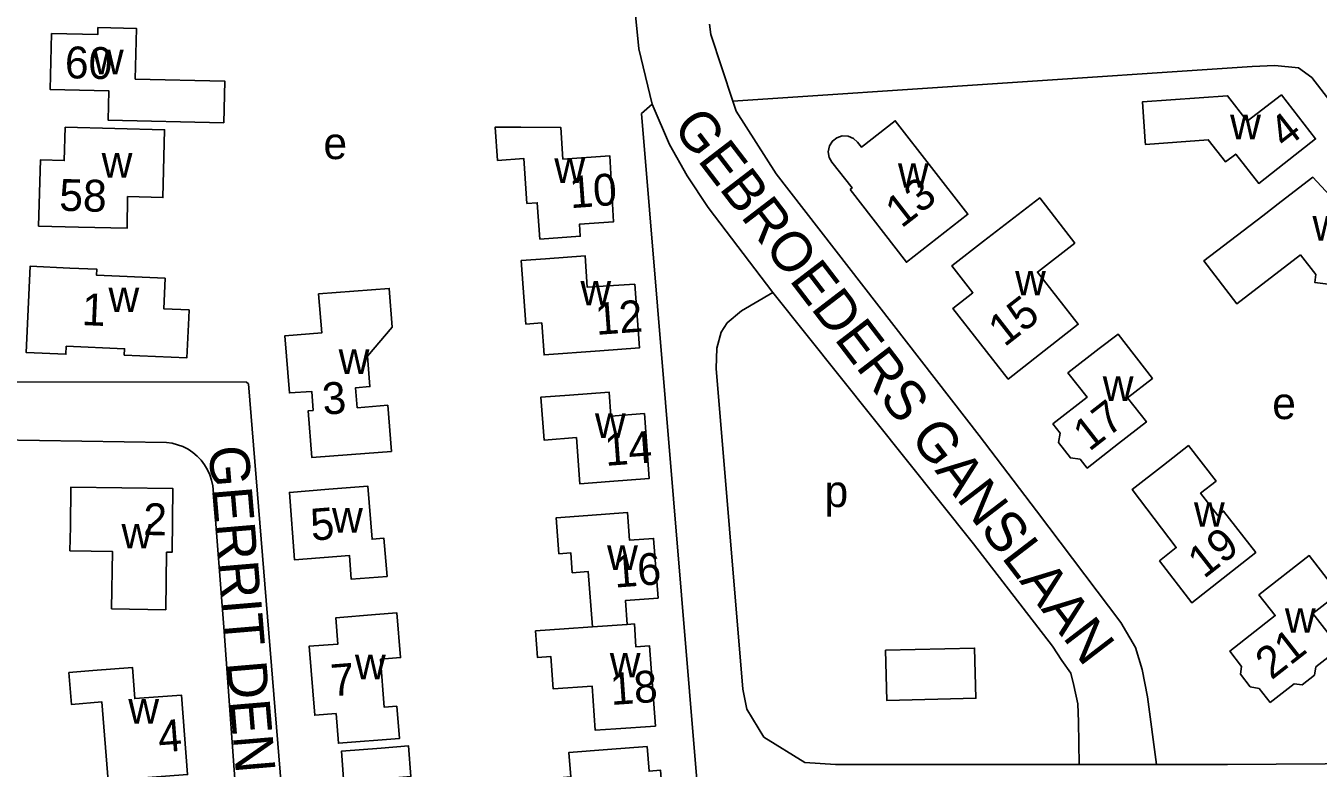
# Model space of a CAD drawing. Extents: x 156721 to 158827, y 386657 to 388950.
# Drawn here: x 158252.9 to 158415.3, y 387600.8 to 387694 of the extents above; entities that cross this region are included whole.
import ezdxf

# ---------------------------------------------------------------- set-up
doc = ezdxf.new("R2010")
doc.units = 0
for name, color, linetype in [('BLT_Basislijn', 7, 'Continuous'), ('BLT_Bebouwing', 7, 'Continuous'), ('BLT_Centroide', 7, 'Continuous'), ('BLT_Huisnummer', 7, 'Continuous'), ('BLT_Onderverdeling_panden', 7, 'Continuous'), ('BLT_Straatnaam', 7, 'Continuous')]:
    doc.layers.add(name, color=color, linetype=linetype)

msp = doc.modelspace()

# ---------------------------------------------------------------- linework, layer by layer
at = {"layer": 'BLT_Basislijn'}
for p, q in [((158270.59, 387641.69), (158233.87, 387642.27)), ((158276.47, 387635.81), (158277.84, 387617.97)), ((158283.92, 387534.66), (158277.84, 387617.97)), ((158385.24, 387601.28), (158394.96, 387601.28))]:
    msp.add_line(p, q, dxfattribs=at)
for points in [[(158331.61, 387684.16), (158329.92, 387691.11), (158327.69, 387713.57), (158325.62, 387716.63), (158322.75, 387717.43), (158319.65, 387717.59), (158249.95, 387717.76)], [(158341.75, 387684.53), (158338.99, 387692.89), (158338.81, 387694.19)], [(158341.75, 387684.53), (158406.99, 387688.87), (158409.83, 387689.02), (158412.81, 387688.72), (158414.45, 387687.52), (158443.84, 387649.45), (158458.24, 387631.46), (158460.33, 387628.78), (158461.37, 387623.55), (158461.08, 387617.73), (158461.22, 387601.86)], [(158394.96, 387601.28), (158393.82, 387609.78), (158393.15, 387613.21), (158392.33, 387615.97), (158390.46, 387619.11), (158379.89, 387633.11), (158372.66, 387642.56), (158347.18, 387675.42), (158342.17, 387683.26), (158341.75, 387684.53)], [(158331.61, 387684.16), (158330.27, 387682.97), (158337.29, 387598.34), (158342.49, 387594.21), (158431.88, 387594.8), (158432.5, 387594.66), (158434.94, 387592.24), (158434.85, 387566.34), (158432.92, 387555.36), (158430.15, 387548.17), (158421.36, 387530.67), (158420.31, 387528.76), (158417.02, 387526.27), (158293.15, 387534.97), (158290, 387537.72), (158280.9, 387649.05), (158280.63, 387649.25), (158242.83, 387649.3)], [(158331.61, 387684.16), (158333.76, 387679.1), (158336, 387675.16), (158338.65, 387671.18), (158346.78, 387660.53)], [(158346.78, 387660.53), (158342.83, 387658.21), (158341.02, 387656.7), (158340.29, 387655.56), (158339.73, 387653.53), (158339.66, 387650.98), (158343.01, 387610.73), (158343.48, 387608.22), (158345.62, 387604.72), (158350.79, 387601.54), (158354.62, 387601.3), (158385.24, 387601.28)], [(158385.24, 387601.28), (158385.17, 387606.64), (158385.09, 387608.88), (158384.57, 387611.2), (158384.2, 387612.76), (158383.08, 387614.33), (158381.89, 387616.12), (158371.96, 387628.96), (158346.78, 387660.53)], [(158270.59, 387641.69), (158271.3, 387641.6), (158272, 387641.42), (158272.67, 387641.17), (158273.31, 387640.84), (158273.9, 387640.44), (158274.46, 387639.98), (158274.95, 387639.47), (158275.39, 387638.9), (158275.75, 387638.28), (158276.05, 387637.63), (158276.27, 387636.95), (158276.42, 387636.25), (158276.47, 387635.81)], [(158394.96, 387601.28), (158396.6, 387601.27), (158403.89, 387601.3), (158452.92, 387601.61), (158461.22, 387601.86)]]:
    msp.add_lwpolyline(points, dxfattribs=at)
msp.add_lwpolyline([(158360.91, 387615.62), (158372.11, 387615.89), (158372.26, 387609.6), (158361.06, 387609.33)], close=True, dxfattribs=at)
at = {"layer": 'BLT_Bebouwing'}
for points in [[(158266.67, 387687.29), (158266.82, 387693.65), (158261.98, 387693.77), (158261.96, 387692.88), (158256.16, 387693.02), (158255.97, 387686), (158263.35, 387685.83), (158263.27, 387682.16), (158277.8, 387681.82), (158277.93, 387687.02), (158266.67, 387687.29)], [(158411, 387676.71), (158407.79, 387674.2), (158404.91, 387677.89), (158403.63, 387676.9), (158401.46, 387679.69), (158393.56, 387679.1), (158393.54, 387679.47), (158393.21, 387684.46), (158403.89, 387685.21), (158406.36, 387682.02), (158410.64, 387685.31), (158414.93, 387679.8), (158411, 387676.71)], [(158257.86, 387681.27), (158270.36, 387680.95), (158270.14, 387672.43), (158265.72, 387672.55), (158265.64, 387668.58), (158259.53, 387668.73), (158254.53, 387668.86), (158254.77, 387677.15), (158257.76, 387677.08), (158257.86, 387681.27)], [(158317.5, 387667.22), (158317.17, 387671.78), (158315.88, 387671.69), (158315.48, 387677.34), (158312.18, 387677.1), (158311.89, 387681.27), (158315.11, 387681.25), (158320.11, 387681.23), (158320.39, 387677.26), (158326.27, 387677.68), (158326.75, 387669.39), (158322.47, 387669.08), (158322.56, 387667.58), (158317.5, 387667.22)], [(158357.39, 387679.39), (158357.88, 387678.77), (158362.14, 387682.08), (158371.26, 387670.33), (158363.55, 387664.32), (158356.47, 387673.46)], [(158357.39, 387679.39), (158356.89, 387679.85), (158356.21, 387680.14), (158355.46, 387680.16), (158354.78, 387679.94), (158354.26, 387679.53), (158353.87, 387678.93), (158353.72, 387678.19), (158353.83, 387677.46), (158354.16, 387676.87)], [(158356.47, 387673.46), (158356.71, 387673.65), (158354.16, 387676.87)], [(158421.52, 387663.23), (158425.44, 387666.33), (158419.04, 387674.51), (158416.71, 387672.71), (158414.59, 387674.98), (158410.62, 387671.94), (158408.29, 387670.16)], [(158380.27, 387652.73), (158385.13, 387656.53), (158379.99, 387663.07), (158384.69, 387666.71), (158380.29, 387672.39), (158373.21, 387666.94), (158369.25, 387663.88), (158371.9, 387660.49), (158369.39, 387658.51), (158376.33, 387649.65), (158380.27, 387652.73)], [(158408.29, 387670.16), (158400.9, 387664.51), (158405.04, 387659.11), (158413.03, 387665.23)], [(158325.02, 387653.21), (158318.03, 387652.69), (158317.74, 387656.7), (158315.74, 387656.55), (158315.16, 387664.52), (158318.2, 387664.75), (158323.18, 387665.13), (158323.44, 387661.17), (158329.42, 387661.56), (158330.01, 387653.57), (158325.02, 387653.21)], [(158413.03, 387665.23), (158414.95, 387662.77), (158414.83, 387661.78), (158419.9, 387661.15), (158420.01, 387662.04), (158421.52, 387663.23)], [(158273.39, 387657.33), (158273.44, 387658.33), (158270.25, 387658.47), (158270.42, 387662.3), (158261.82, 387662.68), (158261.85, 387663.44), (158258.46, 387663.59), (158253.46, 387663.81), (158252.97, 387652.99), (158257.97, 387652.77), (158258.01, 387653.78), (158265.33, 387653.46), (158265.29, 387652.67), (158273.16, 387652.33), (158273.39, 387657.33)], [(158293.85, 387640.18), (158298.84, 387640.58), (158298.38, 387646.36), (158294.55, 387646.05), (158294.35, 387648.57), (158296.16, 387648.71), (158295.86, 387652.53), (158298.96, 387656.15), (158298.57, 387661.04), (158289.71, 387660.35), (158290.1, 387655.45), (158285.48, 387655.09), (158286.04, 387647.92), (158288.84, 387648.11), (158289.01, 387645.72), (158288.4, 387645.68), (158288.86, 387639.79), (158293.85, 387640.18)], [(158390.2, 387641.56), (158393.69, 387644.27), (158391.33, 387647.3), (158394.44, 387649.73), (158390.12, 387655.3), (158387.77, 387653.49), (158383.82, 387650.43), (158386.24, 387647.37), (158381.95, 387644.03), (158382.84, 387642.87), (158382.66, 387641.68), (158384.13, 387639.76), (158385.36, 387639.61), (158386.26, 387638.48), (158390.2, 387641.56)], [(158326.23, 387636.79), (158331.22, 387637.16), (158330.62, 387645.32), (158326.41, 387645.01), (158326.19, 387648.02), (158321.2, 387647.65), (158317.63, 387647.39), (158318.03, 387642), (158322.08, 387642.3), (158322.5, 387636.52), (158326.23, 387636.79)], [(158403.31, 387624.67), (158399.38, 387621.59), (158395.35, 387626.84), (158397.44, 387628.51), (158391.88, 387635.79), (158395.83, 387638.86), (158398.97, 387641.31), (158402.44, 387636.86), (158400.48, 387635.33), (158402.66, 387632.53), (158403.37, 387633.09), (158407.43, 387627.89), (158403.31, 387624.67)], [(158263.7, 387620.83), (158270.5, 387620.71), (158270.61, 387627.92), (158271.3, 387627.91), (158271.4, 387635.9), (158258.59, 387636.09), (158258.52, 387631.09), (158258.47, 387628.1), (158263.8, 387628.02), (158263.7, 387620.83)], [(158298.3, 387624.89), (158297.91, 387629.67), (158296.42, 387629.55), (158295.88, 387636.23), (158291.01, 387635.84), (158286.03, 387635.43), (158286.69, 387626.96), (158293.57, 387627.52), (158293.81, 387624.53), (158298.3, 387624.89)], [(158328.47, 387618.86), (158328.25, 387621.85), (158332.35, 387622.16), (158331.78, 387629.65), (158328.77, 387629.42), (158328.5, 387632.91), (158323.52, 387632.53), (158319.54, 387632.23), (158319.88, 387627.73), (158321.38, 387627.85), (158321.56, 387625.35), (158323.57, 387625.5), (158324.1, 387618.55)], [(158409.22, 387609.05), (158407.83, 387610.84), (158406.73, 387611.03), (158405.49, 387612.62), (158405.63, 387613.6), (158404.18, 387615.52), (158409.86, 387619.98), (158407.81, 387622.57), (158414.14, 387627.49), (158417.83, 387622.75), (158414.59, 387620.23), (158417.97, 387615.88), (158414.95, 387613.52), (158414.81, 387612.51), (158413.25, 387611.3), (158412.23, 387611.4), (158409.22, 387609.05)], [(158296.87, 387620.09), (158291.88, 387619.69), (158292.14, 387616.39), (158288.52, 387616.15), (158289.21, 387607.46), (158291.9, 387607.67), (158292.2, 387603.94), (158299.88, 387604.55), (158299.55, 387608.59)], [(158299.55, 387608.59), (158297.96, 387608.46), (158297.48, 387614.49), (158300, 387614.69), (158299.55, 387620.3), (158296.87, 387620.09)], [(158327.02, 387605.77), (158324.45, 387605.59), (158324.07, 387611.11), (158319.18, 387610.76), (158318.88, 387614.82), (158317.2, 387614.7), (158316.96, 387618.04), (158320.57, 387618.3), (158324.1, 387618.55)], [(158328.47, 387618.86), (158329.37, 387618.93), (158329.57, 387616.04), (158331.27, 387616.16), (158332.01, 387606.11), (158327.02, 387605.77)], [(158268.27, 387599.63), (158263.27, 387599.23), (158262.48, 387609.13), (158258.65, 387608.83), (158258.34, 387612.82), (158261.34, 387613.06), (158266.32, 387613.46), (158266.61, 387609.55), (158272.48, 387609.99), (158273.25, 387600.02), (158268.27, 387599.63)], [(158300.15, 387588), (158299.26, 387599.62), (158301.29, 387599.78), (158301, 387603.61), (158297.57, 387603.35), (158292.59, 387602.97), (158292.83, 387599.47), (158291.34, 387599.37), (158291.51, 387597.58), (158288.99, 387597.41), (158289.65, 387588.73), (158295.35, 387589.17), (158295.47, 387587.64), (158300.15, 387588)], [(158330.34, 387589.52), (158330.12, 387592.36), (158319.58, 387591.56), (158318.97, 387599.54), (158321.37, 387599.72), (158321.14, 387602.8), (158325.98, 387603.16), (158330.96, 387603.54), (158331.22, 387600.43), (158332.67, 387600.56), (158333.28, 387592.58), (158333.09, 387592.36), (158332.89, 387592.53), (158330.34, 387589.52)]]:
    msp.add_lwpolyline(points, dxfattribs=at)
at = {"layer": 'BLT_Onderverdeling_panden'}
msp.add_line((158328.47, 387618.86), (158324.1, 387618.55), dxfattribs=at)

# ---------------------------------------------------------------- texts
at = {"layer": 'BLT_Centroide'}
for s, p in [('w', (158261.35, 387687.91)), ('w', (158404.2, 387679.75)), ('e', (158290.31, 387677.26)), ('w', (158262.45, 387674.94)), ('w', (158319.31, 387674.28)), ('w', (158362.48, 387673.66)), ('w', (158414.55, 387667.03)), ('w', (158377.19, 387660.16)), ('w', (158322.59, 387658.91)), ('w', (158263.31, 387658.06)), ('w', (158292.22, 387650.3)), ('w', (158388.2, 387646.91)), ('e', (158409.49, 387644.63)), ('w', (158324.42, 387642.27)), ('p', (158353.25, 387633.59)), ('w', (158399.66, 387631.12)), ('w', (158291.39, 387630.38)), ('w', (158264.94, 387628.41)), ('w', (158325.94, 387625.7)), ('w', (158411.08, 387617.81)), ('w', (158294.27, 387611.98)), ('w', (158326.28, 387612.22)), ('w', (158265.8, 387606.42))]:
    msp.add_text(s, height=4, dxfattribs=at).set_placement(p)
at = {"layer": 'BLT_Huisnummer'}
for s, rotation, p in [('60', 358.6497, (158257.8, 387687.42)), ('4', 38.0459, (158411.12, 387678.44)), ('58', 358.5288, (158257.09, 387670.78)), ('10', 4.1427, (158321.35, 387671.09)), ('13', 37.9022, (158362.91, 387668.5)), ('1', 357.478, (158259.9, 387656.44)), ('15', 37.9996, (158375.85, 387653.6)), ('12', 4.1869, (158324.6, 387655.19)), ('3', 4.5005, (158290.32, 387645.16)), ('17', 37.9333, (158386.5, 387640.48)), ('14', 4.2097, (158325.77, 387638.75)), ('2', 359.1882, (158267.66, 387630.08)), ('5', 4.6209, (158288.84, 387629.36)), ('19', 38.0241, (158400.91, 387624.52)), ('16', 4.3477, (158326.91, 387623.47)), ('21', 38.0028, (158409.39, 387611.81)), ('7', 4.5535, (158291.38, 387609.83)), ('18', 3.9452, (158326.46, 387608.74)), ('4', 4.5086, (158269.68, 387602.78))]:
    msp.add_text(s, height=4, rotation=rotation, dxfattribs=at).set_placement(p)
at = {"layer": 'BLT_Straatnaam'}
for s, rotation, p in [('GEBROEDERS GANSLAAN', 307.4495, (158334.05, 387681.24)), ('GERRIT DEN BRABERLAAN', 274.8139, (158275.87, 387641.12))]:
    msp.add_text(s, height=5, rotation=rotation, dxfattribs=at).set_placement(p)

doc.saveas('drawing.dxf')
